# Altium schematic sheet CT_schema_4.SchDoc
size 296 x 169 mm
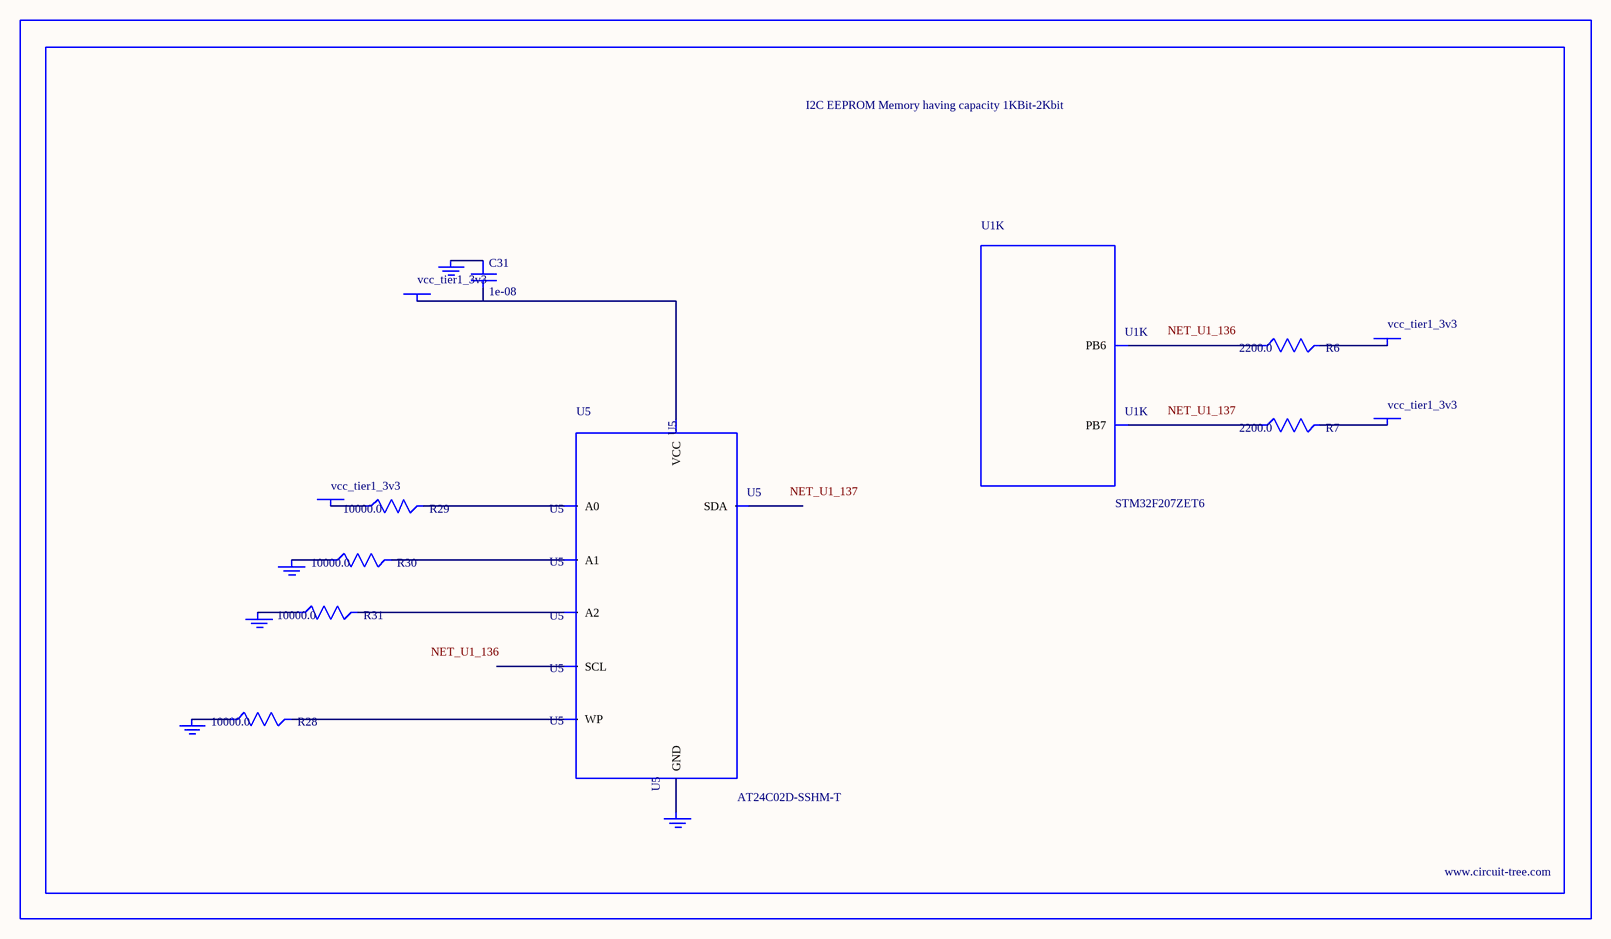
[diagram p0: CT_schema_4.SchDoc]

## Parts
BORDER3  (no value)
C31  1e-08  [C0402]
GND_INSTANCE_3_0  (no value)
GND_INSTANCE_3_1  (no value)
GND_INSTANCE_3_2  (no value)
GND_INSTANCE_3_3  (no value)
GND_INSTANCE_3_4  (no value)
POWER_INSTANCE_3_0  vcc_tier1_3v3
POWER_INSTANCE_3_1  vcc_tier1_3v3
POWER_INSTANCE_3_2  vcc_tier1_3v3
POWER_INSTANCE_3_3  vcc_tier1_3v3
R6  2200.0  [R0603]
R7  2200.0  [R0603]
R28  10000.0  [R0603]
R29  10000.0  [R0603]
R30  10000.0  [R0603]
R31  10000.0  [R0603]
U1  STM32F207ZET6  [LQFP144]  (part K of 13)
U5  AT24C02D-SSHM-T  [AT24C02D]

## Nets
NetC31_1: C31.1 GND_INSTANCE_3_3.0(GND)
NetC31_2: C31.2 POWER_INSTANCE_3_1.0(PWR) U5.8(VCC)
NetGND_INSTANCE_3_0_0: GND_INSTANCE_3_0.0(GND) R30.1
NetGND_INSTANCE_3_1_0: GND_INSTANCE_3_1.0(GND) R31.1
NetGND_INSTANCE_3_2_0: GND_INSTANCE_3_2.0(GND) R28.1
NetGND_INSTANCE_3_4_0: GND_INSTANCE_3_4.0(GND) U5.4(GND)
NetPOWER_INSTANCE_3_0_0: POWER_INSTANCE_3_0.0(PWR) R29.1
NetPOWER_INSTANCE_3_2_0: POWER_INSTANCE_3_2.0(PWR) R6.2
NetPOWER_INSTANCE_3_3_0: POWER_INSTANCE_3_3.0(PWR) R7.2
NetR6_1: R6.1 U1.136(PB6)
NetR7_1: R7.1 U1.137(PB7)
NetR28_2: R28.2 U5.7(WP)
NetR29_2: R29.2 U5.1(A0)
NetR30_2: R30.2 U5.2(A1)
NetR31_2: R31.2 U5.3(A2)

Not connected (* = marked no-connect by the designer): U5 5(SDA) 6(SCL)

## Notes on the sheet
- Labels drawn without touching a wire or pin: NET_U1_136, NET_U1_137

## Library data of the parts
BORDER3 = BORDER_PAGE3
C31 = C0402C103K3RAC
GND_INSTANCE_3_0-GND_INSTANCE_3_4 = GND
POWER_INSTANCE_3_0-POWER_INSTANCE_3_3 = PWR
R6 R7 = RC0603JR-072K2L
R28-R31 = RC0603JR-0710KL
